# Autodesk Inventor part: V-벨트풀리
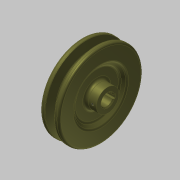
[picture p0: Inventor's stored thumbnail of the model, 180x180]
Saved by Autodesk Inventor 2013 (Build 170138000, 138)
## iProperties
Company: 한국ATC센터
Created: 2015-12
Part Number: V-벨트풀리
Document SubType Name: Modeling
Designer: mdu
Density: 7.25 g/cm^3
Mass: 588.281 g
Surface Area: 211.374 cm^2
Volume: 81.1422 cm^3
Material: 주철
Author: mdu
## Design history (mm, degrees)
sketch "스케치1"
  geometry: L1 (-13, 0)-(13, 0); L2 (-13, 0)-(-13, 11.5); L3 (-13, 11.5)-(-9, 11.5); L4 (-9, 11.5)-(-9, 23); L5 (-9, 23)-(-13, 27); L6 (-13, 27)-(-13, 42.7); L7 (-13, 42.7)-(-8.325, 42.7); L8 (-8.325, 42.7)-(-5.574, 33.7); L9 (-5.574, 33.7)-(-1.426, 33.7); L10 (-1.426, 33.7)-(1.325, 42.7); L11 (1.325, 42.7)-(6, 42.7); L12 (6, 42.7)-(6, 27); L13 (6, 27)-(2, 23); L14 (2, 23)-(2, 11.5); L15 (2, 11.5)-(13, 11.5); L16 (13, 11.5)-(13, 0); L17 (-7.5, 40)-(0.5, 40); 2 further points
  constraints: 34 end point, 6 parallel, 5 collinear, 5 equal length, 4 perpendicular, 2 point on line, 1 coincident, 1 horizontal, 1 midpoint
  dimensions: "d0" = 26 distance of L1.start L1.end; "d1" = 2.7 distance between parallel lines of L7 L17; "d2" = 6.3 distance between parallel lines of L9 L17; "d3" = 8 distance of L17.start L17.end; "d4" = 34 deg angle of L10 L8; "d5" = 19 distance between parallel lines of L12 L6; "d7" = 23 diameter of L15 L1; "d8" = 46 diameter of L13.end L1; "d9" = 54 diameter of L12.end L1; "d10" = 4 distance between parallel lines of L2 L4; "d11" = 80 diameter of L17 L1
revolve "회전1" sketch "스케치1" stored, may be unused: angle "d12" = 90 deg
sketch "스케치2"
  geometry: L1 (-2, 5.657)-(-2, 7.8); L2 (-2, 7.8)-(2, 7.8); L3 (2, 7.8)-(2, 5.657); A1 r 6 centre (0, 0) between (-2, 5.657) and (2, 5.657); 1 further point
  constraints: 6 end point, 2 parallel, 2 point on circle, 1 centre point, 1 coincident, 1 perpendicular, 1 vertical
  dimensions: "d13" = 12 diameter of A1; "d14" = 13.8 dimension on A1 L2; "d15" = 4 distance of L1.end L2.end
extrude "돌출1" cut sketch "스케치2" stored distance "d16" = 10; taper "d17" = 0 deg
node "작업 평면1"
sketch "스케치3"
  geometry: L1 (-5.5, 11.5)-(-5.5, -11.5) reference; L2 (20.5, 27)-(20.5, -27) reference; 3 further points
  constraints: 1 horizontal alignment, 1 midpoint
  dimensions: "d18" = 4 distance from line of point (-1.5, 0) L1; "d33" = 22 distance from line of point (-1.5, 0) L2 (derived)
hole "구멍1" sketch "스케치3" at (-1.5, 0) diameter "d19" = 2.459; stored, may be unused: countersink angle "d23" = 90 deg, drill point angle "d25" = 118 deg; dims "d20" = 6, "d21" = 4, "d22" = 2, "d24" = 8
fillet "모깎기1" dims "d26" = 2, "d27" = 0.5, "d28" = 1, "d29" = 3
chamfer "모따기1" distance "d30" = 1; stored, may be unused: second distance "d31" = 2, angle "d32" = 45 deg
sketch "스케치4" dims "d35" = 70
  geometry: C1 r 3 at (0, 35); 2 further points
  constraints: 2 vertical alignment, 1 centre point, 1 coincident, 2 other
  dimensions: "d34" = 6 diameter of C1
extrude "돌출2" join sketch "스케치4" distance "d36" = 10; taper "d37" = 0 deg
fillet "모깎기2" dims "d38" = 0.5, "d39" = 1
node "솔리드1"
